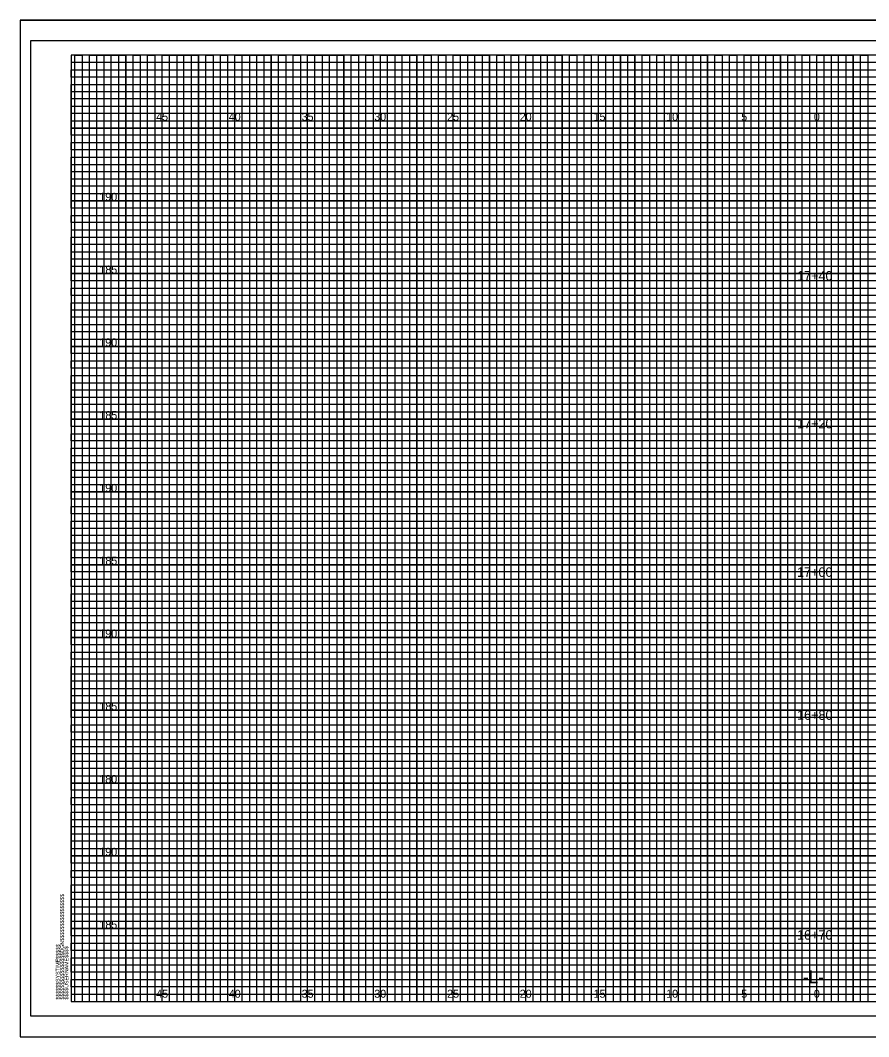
# Model space of a CAD drawing. Extents: x -4 to 103, y -2 to 6583.
# Drawn here: x -3.5 to 54.8, y 635 to 704.8 of the extents above; entities that cross this region are included whole.
import ezdxf

# ---------------------------------------------------------------- set-up
doc = ezdxf.new("R2010")
doc.units = 0
for name, color, linetype in [('Prop XS Alignment Label', 7, 'Continuous'), ('Prop XS Elevation Labels', 7, 'Continuous'), ('Prop XS Offset Labels', 7, 'Continuous'), ('Prop XS Station Labels', 7, 'Continuous'), ('Sheet Cross Section CELL', 7, 'Continuous'), ('Sheet Cross Section Grid Major CELL', 7, 'Continuous'), ('Sheet Cross Section Grid Middle CELL', 7, 'Continuous'), ('Sheet Cutting Line CELL', 7, 'Continuous'), ('Sheet DOT Grid CELL', 7, 'Continuous'), ('Sheet Plot Border Inside CELL', 7, 'Continuous'), ('Sheet Plot Border Outside CELL', 7, 'Continuous')]:
    doc.layers.add(name, color=color, linetype=linetype)

msp = doc.modelspace()

# ---------------------------------------------------------------- linework, layer by layer
at = {"layer": 'Sheet Cross Section CELL'}
msp.add_lwpolyline([(102.5, 702.425), (0, 702.425), (0, 637.425), (102.5, 637.425)], close=True, dxfattribs=at)
at = {"layer": 'Sheet Cross Section Grid Major CELL'}
for points in [[(1.25, 637.425), (1.25, 702.425), (3.75, 702.425), (3.75, 637.425), (6.25, 637.425), (6.25, 702.425), (8.75, 702.425), (8.75, 637.425), (11.25, 637.425), (11.25, 702.425), (13.75, 702.425), (13.75, 637.425), (16.25, 637.425), (16.25, 702.425), (18.75, 702.425), (18.75, 637.425), (21.25, 637.425), (21.25, 702.425), (23.75, 702.425), (23.75, 637.425), (26.25, 637.425), (26.25, 702.425), (28.75, 702.425), (28.75, 637.425), (31.25, 637.425), (31.25, 702.425), (33.75, 702.425), (33.75, 637.425), (36.25, 637.425), (36.25, 702.425), (38.75, 702.425), (38.75, 637.425), (41.25, 637.425), (41.25, 702.425), (43.75, 702.425), (43.75, 637.425), (46.25, 637.425), (46.25, 702.425), (48.75, 702.425), (48.75, 637.425), (51.25, 637.425), (51.25, 702.425), (53.75, 702.425), (53.75, 637.425)], [(102.5, 697.425), (0, 697.425), (0, 699.925), (74.25, 699.925)], [(102.5, 692.425), (0, 692.425), (0, 694.925), (102.5, 694.925)], [(102.5, 687.425), (0, 687.425), (0, 689.925), (102.5, 689.925)], [(102.5, 682.425), (0, 682.425), (0, 684.925), (102.5, 684.925)], [(102.5, 677.425), (0, 677.425), (0, 679.925), (102.5, 679.925)], [(102.5, 672.425), (0, 672.425), (0, 674.925), (102.5, 674.925)], [(102.5, 667.425), (0, 667.425), (0, 669.925), (102.5, 669.925)], [(102.5, 662.425), (0, 662.425), (0, 664.925), (102.5, 664.925)], [(102.5, 657.425), (0, 657.425), (0, 659.925), (102.5, 659.925)], [(102.5, 652.425), (0, 652.425), (0, 654.925), (102.5, 654.925)], [(102.5, 647.425), (0, 647.425), (0, 649.925), (102.5, 649.925)], [(102.5, 642.425), (0, 642.425), (0, 644.925), (102.5, 644.925)], [(0, 639.925), (102.5, 639.925)]]:
    msp.add_lwpolyline(points, dxfattribs=at)
at = {"layer": 'Sheet Cross Section Grid Middle CELL'}
for points in [[(0, 699.425), (0, 700.425), (74.25, 700.425), (74.25, 700.925), (0, 700.925), (0, 701.425), (74.25, 701.425), (74.25, 701.925), (0, 701.925)], [(0.25, 637.425), (0.25, 702.425), (0.75, 702.425), (0.75, 637.425), (1.75, 637.425), (1.75, 702.425), (2.25, 702.425), (2.25, 637.425), (2.75, 637.425), (2.75, 702.425), (3.25, 702.425), (3.25, 637.425), (4.25, 637.425), (4.25, 702.425), (4.75, 702.425), (4.75, 637.425), (5.25, 637.425), (5.25, 702.425), (5.75, 702.425), (5.75, 637.425), (6.75, 637.425), (6.75, 702.425), (7.25, 702.425), (7.25, 637.425), (7.75, 637.425), (7.75, 702.425), (8.25, 702.425), (8.25, 637.425), (9.25, 637.425), (9.25, 702.425), (9.75, 702.425), (9.75, 637.425), (10.25, 637.425), (10.25, 702.425), (10.75, 702.425), (10.75, 637.425), (11.75, 637.425), (11.75, 702.425), (12.25, 702.425), (12.25, 637.425), (12.75, 637.425), (12.75, 702.425), (13.25, 702.425), (13.25, 637.425), (14.25, 637.425), (14.25, 702.425), (14.75, 702.425), (14.75, 637.425), (15.75, 637.425), (15.25, 637.425), (15.25, 702.425), (15.75, 702.425), (15.75, 637.425), (16.75, 637.425), (16.75, 702.425), (17.25, 702.425), (17.25, 637.425), (17.75, 637.425), (17.75, 702.425), (18.25, 702.425), (18.25, 637.425), (19.25, 637.425), (19.25, 702.425), (19.75, 702.425), (19.75, 637.425), (20.25, 637.425), (20.25, 702.425), (20.75, 702.425), (20.75, 637.425), (21.75, 637.425), (21.75, 702.425), (22.25, 702.425), (22.25, 637.425), (22.75, 637.425), (22.75, 702.425), (23.25, 702.425), (23.25, 637.425), (24.25, 637.425), (24.25, 702.425), (24.75, 702.425), (24.75, 637.425), (25.25, 637.425), (25.25, 702.425), (25.75, 702.425), (25.75, 637.425), (26.75, 637.425), (26.75, 702.425), (27.25, 702.425), (27.25, 637.425), (27.75, 637.425), (27.75, 702.425), (28.25, 702.425), (28.25, 637.425), (29.25, 637.425), (29.25, 702.425), (29.75, 702.425), (29.75, 637.425), (30.25, 637.425), (30.25, 702.425), (30.75, 702.425), (30.75, 637.425)], [(30.75, 637.425), (31.75, 637.425), (31.75, 702.425), (32.25, 702.425), (32.25, 637.425), (32.75, 637.425), (32.75, 702.425), (33.25, 702.425), (33.25, 637.425), (34.25, 637.425), (34.25, 702.425), (34.75, 702.425), (34.75, 637.425), (35.25, 637.425), (35.25, 702.425), (35.75, 702.425), (35.75, 637.425), (36.75, 637.425), (36.75, 702.425), (37.25, 702.425), (37.25, 637.425), (37.75, 637.425), (37.75, 702.425), (37.75, 637.425)], [(38.25, 702.425), (38.25, 637.425), (39.25, 637.425), (39.25, 702.425), (39.75, 702.425), (39.75, 637.425), (40.25, 637.425), (40.25, 702.425), (40.75, 702.425), (40.75, 637.425), (41.75, 637.425), (41.75, 702.425), (42.25, 702.425), (42.25, 637.425), (42.75, 637.425), (42.75, 702.425), (43.25, 702.425), (43.25, 637.425), (43.75, 637.425), (44.25, 637.425), (44.25, 702.425), (44.75, 702.425), (44.75, 637.425), (45.25, 637.425), (45.25, 702.425), (45.75, 702.425), (45.75, 637.425), (46.75, 637.425), (46.75, 702.425), (47.25, 702.425), (47.25, 637.425), (47.75, 637.425), (47.75, 702.425), (48.25, 702.425), (48.25, 637.425), (49.25, 637.425), (49.25, 702.425), (49.75, 702.425), (49.75, 637.425), (50.25, 637.425), (50.25, 702.425), (50.75, 702.425), (50.75, 637.425), (51.75, 637.425), (51.75, 702.425), (52.25, 702.425), (52.25, 637.425), (52.75, 637.425), (52.75, 702.425), (53.25, 702.425), (53.25, 637.425), (54.25, 637.425), (54.25, 702.425), (54.75, 702.425), (54.75, 637.425), (55.25, 637.425)], [(102.5, 699.425), (0, 699.425)], [(102.5, 698.425), (0, 698.425), (0, 698.925), (102.5, 698.925)], [(102.5, 696.925), (0, 696.925), (0, 697.925), (102.5, 697.925)], [(102.5, 695.925), (0, 695.925), (0, 696.425), (102.5, 696.425)], [(102.5, 694.425), (0, 694.425), (0, 695.425), (102.5, 695.425)], [(102.5, 693.425), (0, 693.425), (0, 693.925), (102.5, 693.925)], [(102.5, 691.925), (0, 691.925), (0, 692.925), (102.5, 692.925)], [(102.5, 690.925), (0, 690.925), (0, 691.425), (102.5, 691.425)], [(0, 690.425), (102.5, 690.425)], [(102.5, 689.425), (0, 689.425)], [(102.5, 688.425), (0, 688.425), (0, 688.925), (102.5, 688.925)], [(102.5, 686.925), (0, 686.925), (0, 687.925), (102.5, 687.925)], [(102.5, 685.925), (0, 685.925), (0, 686.425), (102.5, 686.425)], [(102.5, 684.425), (0, 684.425), (0, 685.425), (102.5, 685.425)], [(102.5, 683.425), (0, 683.425), (0, 683.925), (102.5, 683.925)], [(102.5, 681.925), (0, 681.925), (0, 682.925), (102.5, 682.925)], [(102.5, 680.925), (0, 680.925), (0, 681.425), (102.5, 681.425)], [(102.5, 679.425), (0, 679.425), (0, 680.425), (102.5, 680.425)], [(102.5, 678.425), (0, 678.425), (0, 678.925), (102.5, 678.925)], [(102.5, 676.925), (0, 676.925), (0, 677.925), (102.5, 677.925)], [(102.5, 675.925), (0, 675.925), (0, 676.425), (102.5, 676.425)], [(102.5, 674.425), (0, 674.425), (0, 675.425), (102.5, 675.425)], [(102.5, 673.425), (0, 673.425), (0, 673.925), (102.5, 673.925)], [(102.5, 671.925), (0, 671.925), (0, 672.925), (102.5, 672.925)], [(102.5, 670.925), (0, 670.925), (0, 671.425), (102.5, 671.425)], [(102.5, 669.425), (0, 669.425), (0, 670.425), (102.5, 670.425)], [(102.5, 668.425), (0, 668.425), (0, 668.925)], [(0, 668.925), (102.5, 668.925)], [(102.5, 666.925), (0, 666.925), (0, 667.925), (102.5, 667.925)], [(102.5, 665.925), (0, 665.925), (0, 666.425), (102.5, 666.425)], [(102.5, 664.425), (0, 664.425), (0, 665.425), (102.5, 665.425)], [(102.5, 663.425), (0, 663.425), (0, 663.925), (102.5, 663.925)], [(102.5, 661.925), (0, 661.925), (0, 662.925), (102.5, 662.925)], [(102.5, 660.925), (0, 660.925), (0, 661.425), (102.5, 661.425)], [(102.5, 659.425), (0, 659.425), (0, 660.425), (102.5, 660.425)], [(102.5, 658.425), (0, 658.425), (0, 658.925), (102.5, 658.925)], [(102.5, 656.925), (0, 656.925), (0, 657.925), (102.5, 657.925)], [(102.5, 655.925), (0, 655.925), (0, 656.425), (102.5, 656.425)], [(102.5, 654.425), (0, 654.425), (0, 655.425), (102.5, 655.425)], [(102.5, 653.425), (0, 653.425), (0, 653.925), (102.5, 653.925)], [(102.5, 651.925), (0, 651.925), (0, 652.925), (102.5, 652.925)], [(102.5, 650.925), (0, 650.925), (0, 651.425), (102.5, 651.425)], [(102.5, 649.425), (0, 649.425), (0, 650.425), (102.5, 650.425)], [(102.5, 648.425), (0, 648.425), (0, 648.925), (102.5, 648.925)], [(102.5, 646.925), (0, 646.925), (0, 647.925), (102.5, 647.925)], [(102.5, 645.925), (0, 645.925), (0, 646.425), (102.5, 646.425)], [(102.5, 644.425), (0, 644.425), (0, 645.425), (102.5, 645.425)], [(102.5, 643.425), (0, 643.425), (0, 643.925), (102.5, 643.925)], [(102.5, 641.925), (0, 641.925), (0, 642.925), (102.5, 642.925)], [(102.5, 640.925), (0, 640.925), (0, 641.425), (102.5, 641.425)], [(102.5, 639.425), (0, 639.425), (0, 640.425), (102.5, 640.425)], [(102.5, 638.425), (0, 638.425), (0, 638.925), (102.5, 638.925)], [(0, 637.925), (102.5, 637.925)]]:
    msp.add_lwpolyline(points, dxfattribs=at)
at = {"layer": 'Sheet Cutting Line CELL'}
for p, q in [((-3.5, 704.825), (103.4, 704.825)), ((-3.5, 704.825), (-3.5, 635)), ((-3.5, 635), (103.4, 635))]:
    msp.add_line(p, q, dxfattribs=at)
at = {"layer": 'Sheet DOT Grid CELL'}
for p, q in [((1.25, 637.425), (1.25, 702.425)), ((3.75, 637.425), (3.75, 702.425)), ((6.25, 637.425), (6.25, 702.425)), ((8.75, 637.425), (8.75, 702.425)), ((11.25, 637.425), (11.25, 702.425)), ((13.75, 637.425), (13.75, 702.425)), ((16.25, 637.425), (16.25, 702.425)), ((18.75, 637.425), (18.75, 702.425)), ((21.25, 637.425), (21.25, 702.425)), ((23.75, 637.425), (23.75, 702.425)), ((26.25, 637.425), (26.25, 702.425)), ((28.75, 637.425), (28.75, 702.425)), ((31.25, 637.425), (31.25, 702.425)), ((33.75, 637.425), (33.75, 702.425)), ((36.25, 637.425), (36.25, 702.425)), ((38.75, 637.425), (38.75, 702.425)), ((41.25, 637.425), (41.25, 702.425)), ((43.75, 637.425), (43.75, 702.425)), ((46.25, 637.425), (46.25, 702.425)), ((48.75, 637.425), (48.75, 702.425)), ((51.25, 637.425), (51.25, 702.425)), ((53.75, 637.425), (53.75, 702.425)), ((0, 699.925), (74.25, 699.925)), ((0, 697.425), (102.5, 697.425)), ((0, 694.925), (102.5, 694.925)), ((0, 692.425), (102.5, 692.425)), ((0, 689.925), (102.5, 689.925)), ((0, 687.425), (102.5, 687.425)), ((0, 684.925), (102.5, 684.925)), ((0, 682.425), (102.5, 682.425)), ((0, 679.925), (102.5, 679.925)), ((0, 677.425), (102.5, 677.425)), ((0, 674.925), (102.5, 674.925)), ((0, 672.425), (102.5, 672.425)), ((0, 669.925), (102.5, 669.925)), ((0, 667.425), (102.5, 667.425)), ((0, 664.925), (102.5, 664.925)), ((0, 662.425), (102.5, 662.425)), ((0, 659.925), (102.5, 659.925)), ((0, 657.425), (102.5, 657.425)), ((0, 654.925), (102.5, 654.925)), ((0, 652.425), (102.5, 652.425)), ((0, 649.925), (102.5, 649.925)), ((0, 647.425), (102.5, 647.425)), ((0, 644.925), (102.5, 644.925)), ((0, 642.425), (102.5, 642.425)), ((0, 639.925), (102.5, 639.925))]:
    msp.add_line(p, q, dxfattribs=at)
at = {"layer": 'Sheet Plot Border Inside CELL'}
msp.add_lwpolyline([(103, 703.425), (-2.8, 703.425), (-2.8, 636.425), (103, 636.425)], close=True, dxfattribs=at)
at = {"layer": 'Sheet Plot Border Outside CELL'}
msp.add_lwpolyline([(103.4, 704.825), (-3.5, 704.825), (-3.5, 635), (103.4, 635)], close=True, dxfattribs=at)

# ---------------------------------------------------------------- texts
at = {"layer": 'Prop XS Alignment Label'}
msp.add_text('-L-', height=0.875, dxfattribs=at).set_placement((50.307, 638.675))
at = {"layer": 'Prop XS Elevation Labels'}
for s, p in [('190', (1.93, 692.425)), ('185', (1.938, 687.425)), ('190', (1.93, 682.425)), ('185', (1.938, 677.425)), ('190', (1.93, 672.425)), ('185', (1.938, 667.425)), ('190', (1.93, 662.425)), ('185', (1.938, 657.425)), ('180', (1.93, 652.425)), ('190', (1.93, 647.425)), ('185', (1.938, 642.425))]:
    msp.add_text(s, height=0.55, dxfattribs=at).set_placement(p)
at = {"layer": 'Prop XS Offset Labels'}
for s, p in [('45', (5.84, 697.925)), ('40', (10.831, 697.925)), ('35', (15.84, 697.925)), ('30', (20.831, 697.925)), ('25', (25.84, 697.925)), ('20', (30.831, 697.925)), ('15', (35.906, 697.925)), ('10', (40.897, 697.925)), ('5', (46.057, 697.925)), ('0', (51.049, 697.925)), ('0', (51.049, 697.925)), ('45', (5.84, 637.675)), ('40', (10.831, 637.675)), ('35', (15.84, 637.675)), ('30', (20.831, 637.675)), ('25', (25.84, 637.675)), ('20', (30.831, 637.675)), ('15', (35.906, 637.675)), ('10', (40.897, 637.675)), ('5', (46.057, 637.675)), ('0', (51.049, 637.675)), ('0', (51.049, 637.675))]:
    msp.add_text(s, height=0.55, dxfattribs=at).set_placement(p)
at = {"layer": 'Prop XS Station Labels'}
for s, p in [('17+40', (49.893, 686.946)), ('17+20', (49.893, 676.795)), ('17+00', (49.893, 666.591)), ('16+80', (49.893, 656.768)), ('16+70', (49.893, 641.665))]:
    msp.add_text(s, height=0.65, dxfattribs=at).set_placement(p)
at = {"layer": 'Sheet Cross Section CELL'}
for s, p in [('$$$$$$$$$$$$$$$$DGN$$$$$$$$$$$$$$$$', (-0.5, 637.55)), ('$$$$$$SYSTIME$$$$$', (-0.797, 637.55)), ('$$$$USERNAME$$$$', (-0.2, 637.55))]:
    msp.add_text(s, height=0.2625, rotation=90, dxfattribs=at).set_placement(p)
at = {"layer": 'Sheet Cross Section Grid Major CELL'}
msp.add_text('040397', height=0.0025, rotation=90, dxfattribs=at).set_placement((-0.001, 702.411))

doc.saveas('drawing.dxf')
